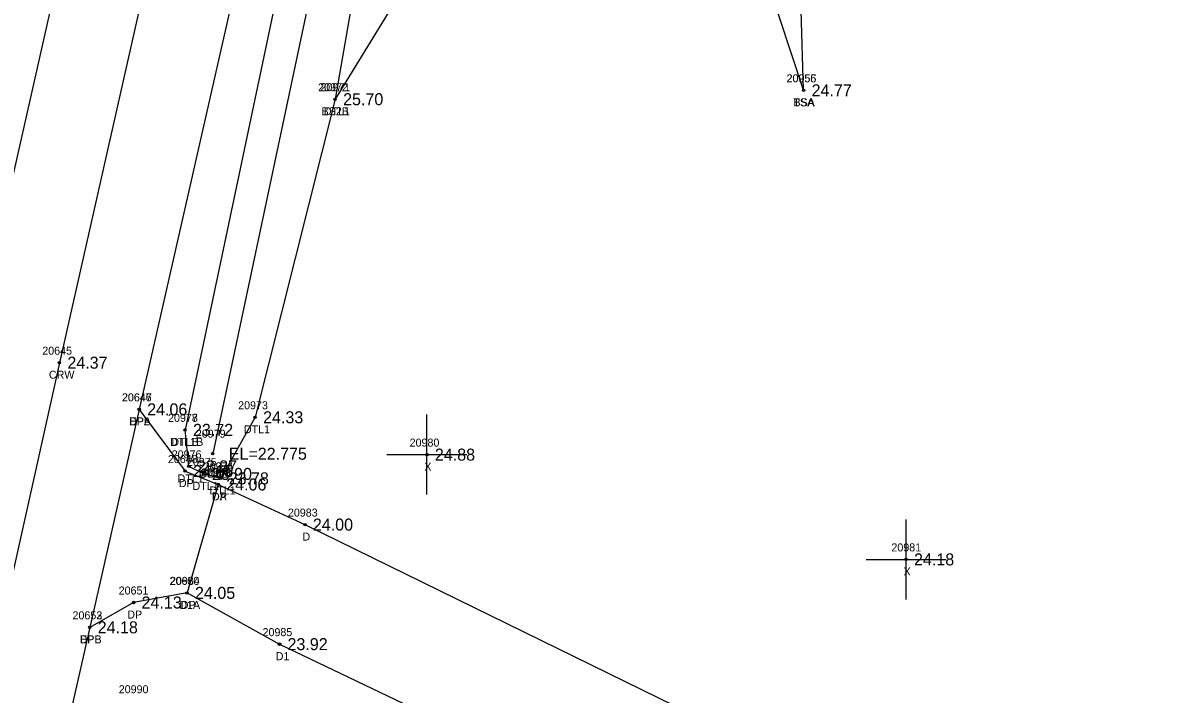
# Model space of a CAD drawing. Extents: x 2655177 to 2656219, y 761780 to 764748.
# Drawn here: x 2655568.1 to 2655710.1, y 762575 to 762658.8 of the extents above; entities that cross this region are included whole.
import ezdxf

# ---------------------------------------------------------------- set-up
doc = ezdxf.new("R2010")
doc.units = 0
for name, color, linetype in [('RD_DTM_BkLn1', 7, 'Continuous'), ('RD_DTM_BkLn2', 7, 'Continuous'), ('RD_DTM_BkLn_txCode', 7, 'Continuous'), ('RD_EX_Driveway', 7, 'Continuous'), ('RD_EX_Driveway_txCode', 7, 'Continuous'), ('RD_EX_H2O', 7, 'Continuous'), ('RD_EX_H2O_txCode', 7, 'Continuous'), ('RD_EX_Misc', 7, 'Continuous'), ('RD_EX_Misc_txCode', 7, 'Continuous'), ('RD_EX_Road', 7, 'Continuous'), ('RD_EX_Road_txCode', 7, 'Continuous'), ('RD_EX_TX_Driveway_ELEV', 7, 'Continuous'), ('RD_EX_TX_H2O_ELEV', 7, 'Continuous'), ('RD_EX_TX_Misc_ELEV', 7, 'Continuous'), ('RD_EX_TX_Road_ELEV', 7, 'Continuous'), ('RD_HC_Survey_ELEV', 7, 'Continuous'), ('RD_HC_Survey_txCode', 7, 'Continuous'), ('RD_SMD_Locator', 7, 'Continuous')]:
    doc.layers.add(name, color=color, linetype=linetype)

msp = doc.modelspace()

# ---------------------------------------------------------------- linework, layer by layer
at = {"layer": 'RD_DTM_BkLn1'}
msp.add_lwpolyline([(2655711.06, 763230.3), (2655703.38, 763195.9), (2655681.97, 763099.65), (2655659.44, 762998.39), (2655637.72, 762903.26), (2655615.94, 762806.28), (2655593.94, 762710.45), (2655572.67, 762616.37), (2655551.12, 762519.58), (2655528.83, 762422.13), (2655507.58, 762326.81), (2655486.01, 762234.2), (2655464.77, 762141.12), (2655442.2, 762047.28), (2655420.99, 761952.95), (2655398.79, 761855.74), (2655384.11, 761791.21)], dxfattribs=at)
at = {"layer": 'RD_DTM_BkLn2'}
for points in [[(2655665.68, 762650.38), (2655659.6, 762668.86), (2655659.02, 762687.89), (2655667.66, 762702.19), (2655703.95, 762737.65)], [(2655665.68, 762650.38), (2655665.08, 762670.35), (2655679.18, 762692.29), (2655707.13, 762724.28), (2655703.95, 762737.65)], [(2655631.19, 762705.65), (2655616.68, 762664.86), (2655607.13, 762649.27)]]:
    msp.add_lwpolyline(points, dxfattribs=at)
at = {"layer": 'RD_EX_Driveway'}
for points in [[(2655582.64, 762610.54), (2655588.38, 762602.83), (2655592.52, 762601.16), (2655588.62, 762587.62), (2655581.94, 762586.42), (2655576.46, 762583.32)], [(2655592.52, 762601.16), (2655603.35, 762596.15), (2655666.52, 762565.25)], [(2655588.62, 762587.62), (2655600.18, 762581.22), (2655656.95, 762554.09)]]:
    msp.add_lwpolyline(points, dxfattribs=at)
at = {"layer": 'RD_EX_H2O'}
for points in [[(2655616.83, 762733.96), (2655609.4, 762707.61), (2655588.37, 762607.98)], [(2655616.83, 762733.96), (2655623.42, 762732.41), (2655617.05, 762706.39), (2655607.13, 762649.27), (2655597.13, 762609.55), (2655592.83, 762601.92), (2655590.72, 762602.48), (2655588.85, 762603.42), (2655588.37, 762607.98)], [(2655619.06, 762730.77), (2655613.49, 762707.16), (2655591.84, 762605)]]:
    msp.add_lwpolyline(points, dxfattribs=at)
at = {"layer": 'RD_EX_Misc'}
for p, q in [((2655618.6, 762599.89), (2655618.6, 762609.89)), ((2655613.6, 762604.89), (2655623.6, 762604.89)), ((2655678.48, 762586.8), (2655678.48, 762596.8)), ((2655673.48, 762591.8), (2655683.48, 762591.8))]:
    msp.add_line(p, q, dxfattribs=at)
at = {"layer": 'RD_EX_Road'}
for points in [[(2655700.99, 763232.28), (2655693.55, 763198.57), (2655671.65, 763102.04), (2655649.04, 763001.06), (2655627.27, 762906.23), (2655605, 762809.37), (2655598.99, 762783.09), (2655583.65, 762714.14), (2655561.97, 762618.32), (2655556.36, 762593.84), (2655548.11, 762557.14), (2655540.1, 762522.48), (2655518.03, 762425.04), (2655496.48, 762329.56), (2655475.55, 762236.62), (2655473.2, 762226.14), (2655466.57, 762197.5), (2655460.06, 762168.16), (2655454.26, 762143.78), (2655432.5, 762049.88), (2655410.7, 761955.51), (2655388.17, 761858.43), (2655373.5, 761793.95)], [(2655722.66, 763227.87), (2655714.47, 763193.23), (2655692.89, 763097.26), (2655670.04, 762995.18), (2655648.57, 762900.67), (2655631.27, 762824.03), (2655626.67, 762802.87), (2655621.78, 762781.91), (2655611.71, 762738.43), (2655604.93, 762708.62), (2655582.64, 762610.54), (2655576.46, 762583.32), (2655561.41, 762517.24)]]:
    msp.add_lwpolyline(points, dxfattribs=at)
at = {"layer": 'RD_SMD_Locator'}
for centre in [(2655665.68, 762650.38), (2655665.68, 762650.38), (2655607.13, 762649.27), (2655607.13, 762649.27), (2655572.67, 762616.37), (2655582.64, 762610.54), (2655582.64, 762610.54), (2655597.13, 762609.55), (2655588.37, 762607.98), (2655588.37, 762607.98), (2655591.84, 762605), (2655618.6, 762604.89), (2655588.85, 762603.42), (2655588.38, 762602.83), (2655590.72, 762602.48), (2655592.83, 762601.92), (2655592.52, 762601.16), (2655592.52, 762601.16), (2655603.35, 762596.15), (2655678.48, 762591.8), (2655588.62, 762587.62), (2655588.62, 762587.62), (2655581.94, 762586.42), (2655576.46, 762583.32), (2655576.46, 762583.32), (2655600.18, 762581.22)]:
    msp.add_circle(centre, 0.15, dxfattribs=at)

# ---------------------------------------------------------------- texts
at = {"layer": 'RD_DTM_BkLn_txCode'}
for s, p in [('20956', (2655663.54, 762651.38)), ('20955', (2655663.56, 762651.38)), ('20971', (2655605.29, 762650.27)), ('TSA', (2655664.4, 762648.38)), ('BSA', (2655664.41, 762648.38)), ('BS2B', (2655605.43, 762647.27))]:
    msp.add_text(s, height=1, dxfattribs=at).set_placement(p)
at = {"layer": 'RD_EX_Driveway_txCode'}
for s, p in [('20647', (2655580.5, 762611.54)), ('DPA', (2655581.38, 762608.54)), ('20648', (2655586.23, 762603.83)), ('20649', (2655590.37, 762602.16)), ('20982', (2655590.4, 762602.16)), ('DP', (2655587.6, 762600.83)), ('DA', (2655591.72, 762599.16)), ('DP', (2655591.74, 762599.16)), ('20983', (2655601.23, 762597.15)), ('D', (2655603.04, 762594.15)), ('20650', (2655586.44, 762588.62)), ('20984', (2655586.5, 762588.62)), ('20651', (2655580.08, 762587.42)), ('D1A', (2655587.66, 762585.62)), ('DP', (2655587.84, 762585.62)), ('20652', (2655574.31, 762584.32)), ('DP', (2655581.16, 762584.42)), ('20985', (2655598.06, 762582.22)), ('DPB', (2655575.2, 762581.32)), ('D1', (2655599.71, 762579.22))]:
    msp.add_text(s, height=1, dxfattribs=at).set_placement(p)
at = {"layer": 'RD_EX_H2O_txCode'}
for s, p in [('20972', (2655605.01, 762650.27)), ('DTL1', (2655605.72, 762647.27)), ('20973', (2655595.01, 762610.55)), ('20977', (2655586.25, 762608.98)), ('20978', (2655586.25, 762608.98)), ('20979', (2655589.72, 762607)), ('DTL1', (2655595.72, 762607.55)), ('DTL1B', (2655586.49, 762605.98)), ('DTLB', (2655586.66, 762605.98)), ('20976', (2655586.71, 762604.42)), ('20975', (2655588.61, 762603.48)), ('ODLB', (2655590.12, 762602)), ('20974', (2655590.71, 762602.92)), ('DTL1', (2655587.44, 762601.42)), ('DTL1', (2655589.31, 762600.48)), ('DTL1', (2655591.42, 762599.92)), ('20990', (2655580.09, 762575.09))]:
    msp.add_text(s, height=1, dxfattribs=at).set_placement(p)
at = {"layer": 'RD_EX_Misc_txCode'}
for s, p in [('20980', (2655616.44, 762605.89)), ('X', (2655618.28, 762602.89)), ('20981', (2655676.65, 762592.8)), ('X', (2655678.17, 762589.8))]:
    msp.add_text(s, height=1, dxfattribs=at).set_placement(p)
at = {"layer": 'RD_EX_Road_txCode'}
for s, p in [('20646', (2655580.48, 762611.54)), ('EPL', (2655581.44, 762608.54)), ('20653', (2655574.31, 762584.32)), ('EPL', (2655575.25, 762581.32))]:
    msp.add_text(s, height=1, dxfattribs=at).set_placement(p)
at = {"layer": 'RD_EX_TX_Driveway_ELEV'}
for s, p in [('24.06', (2655583.64, 762609.79)), ('24.15', (2655589.38, 762602.08)), ('24.06', (2655593.52, 762600.41)), ('24.06', (2655593.52, 762600.41)), ('24.00', (2655604.35, 762595.4)), ('24.05', (2655589.62, 762586.87)), ('24.05', (2655589.62, 762586.87)), ('24.13', (2655582.94, 762585.67)), ('24.18', (2655577.46, 762582.57)), ('23.92', (2655601.18, 762580.47))]:
    msp.add_text(s, height=1.5, dxfattribs=at).set_placement(p)
at = {"layer": 'RD_EX_TX_H2O_ELEV'}
for s, p in [('25.70', (2655608.13, 762648.52)), ('24.33', (2655598.13, 762608.8)), ('23.72', (2655589.37, 762607.23)), ('23.72', (2655589.37, 762607.23)), ('EL=22.775', (2655593.84, 762604.25)), ('23.87', (2655589.85, 762602.67)), ('23.90', (2655591.72, 762601.73)), ('23.78', (2655593.83, 762601.17))]:
    msp.add_text(s, height=1.5, dxfattribs=at).set_placement(p)
at = {"layer": 'RD_EX_TX_Misc_ELEV'}
for s, p in [('25.70', (2655608.13, 762648.52)), ('24.77', (2655666.68, 762649.63)), ('24.77', (2655666.68, 762649.63)), ('24.88', (2655619.6, 762604.14)), ('24.18', (2655679.48, 762591.05))]:
    msp.add_text(s, height=1.5, dxfattribs=at).set_placement(p)
at = {"layer": 'RD_EX_TX_Road_ELEV'}
for s, p in [('24.06', (2655583.64, 762609.79)), ('24.18', (2655577.46, 762582.57))]:
    msp.add_text(s, height=1.5, dxfattribs=at).set_placement(p)
at = {"layer": 'RD_HC_Survey_ELEV'}
msp.add_text('24.37', height=1.5, dxfattribs=at).set_placement((2655573.67, 762615.62))
at = {"layer": 'RD_HC_Survey_txCode'}
for s, p in [('20645', (2655570.53, 762617.37)), ('CRW', (2655571.36, 762614.37))]:
    msp.add_text(s, height=1, dxfattribs=at).set_placement(p)

doc.saveas('drawing.dxf')
